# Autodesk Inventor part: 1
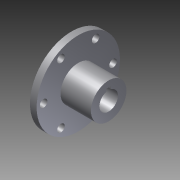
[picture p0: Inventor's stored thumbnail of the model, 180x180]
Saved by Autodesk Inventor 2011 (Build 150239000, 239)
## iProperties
Created: 2011-01
Part Number: 1
Document SubType Name: Modeling
Designer: dfranz
Density: 1 g/cm^3
Author: dfranz
Translation Standard: STEP AP203
FileName: C:/Documents and Settings/Andy Baker/My Documents/AndyMark/Products/Hubs/500_key_hub.stp
PreProcessor: Unknown
PostProcessor: Build: 239, Release: 2011 RTM - Date: Wed 02/17/2010
Sent Units: inch
Uncertainty: 3.93700787401575e-05
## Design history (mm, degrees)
feature "Base1"
node "1"
